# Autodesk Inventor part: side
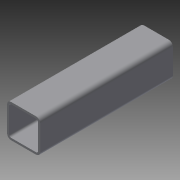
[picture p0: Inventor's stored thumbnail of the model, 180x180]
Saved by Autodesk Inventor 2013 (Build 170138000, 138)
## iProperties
Created: 2008-04
Part Number: side
Document SubType Name: Modeling
Designer: Jayson Martinez
Density: 1 g/cm^3
Material: Generic
Author: Jayson Martinez
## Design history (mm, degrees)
sketch "Sketch1"
  geometry: L1 (6.35, 0)-(44.45, 0); L2 (50.8, 6.35)-(50.8, 44.45); L3 (44.45, 50.8)-(6.35, 50.8); L4 (0, 44.45)-(0, 6.35); L5 (3.175, 6.35)-(3.175, 44.45); L6 (6.35, 47.625)-(44.45, 47.625); L7 (47.625, 44.45)-(47.625, 6.35); L8 (44.45, 3.175)-(6.35, 3.175); A1 r 6.35 centre (6.35, 44.45) between (6.35, 50.8) and (0, 44.45); A2 r 6.35 centre (6.35, 6.35) between (0, 6.35) and (6.35, 0); A3 r 6.35 centre (44.45, 6.35) between (44.45, 0) and (50.8, 6.35); A4 r 6.35 centre (44.45, 44.45) between (50.8, 44.45) and (44.45, 50.8); A5 r 3.175 centre (6.35, 44.45) between (6.35, 47.625) and (3.175, 44.45); A6 r 3.175 centre (44.45, 44.45) between (47.625, 44.45) and (44.45, 47.625); A7 r 3.175 centre (44.45, 6.35) between (44.45, 3.175) and (47.625, 6.35); A8 r 3.175 centre (6.35, 6.35) between (3.175, 6.35) and (6.35, 3.175); 3 further points
  constraints: 16 end point, 16 point on circle, 8 centre point, 8 tangent, 6 point on line, 4 parallel, 3 equal radius, 2 perpendicular, 1 horizontal, 7 other
  dimensions: "d0" = 50.8 distance of point (0, 0) point (50.8, 0) (= MemberWidth); "d1" = 50.8 distance of point (0, 50.8) point (0, 0) (= MemberWidth); "d2" = 6.35 radius of A1 (= 2 x MemberThickness); "d3" = 3.175 distance between parallel lines of L4 L5 (= MemberThickness)
extrude "Extrusion1" new body sketch "Sketch1" distance "d4" = 203.2 (= SideLength); taper "d5" = 0 deg
workplane "Work Plane1"
body "Solid1"
other parameters: "d6" = -25.4 (= -0.5 x MemberWidth), "MemberThickness" = 3.175, "MemberWidth" = 50.8, "SideLength" = 203.2
